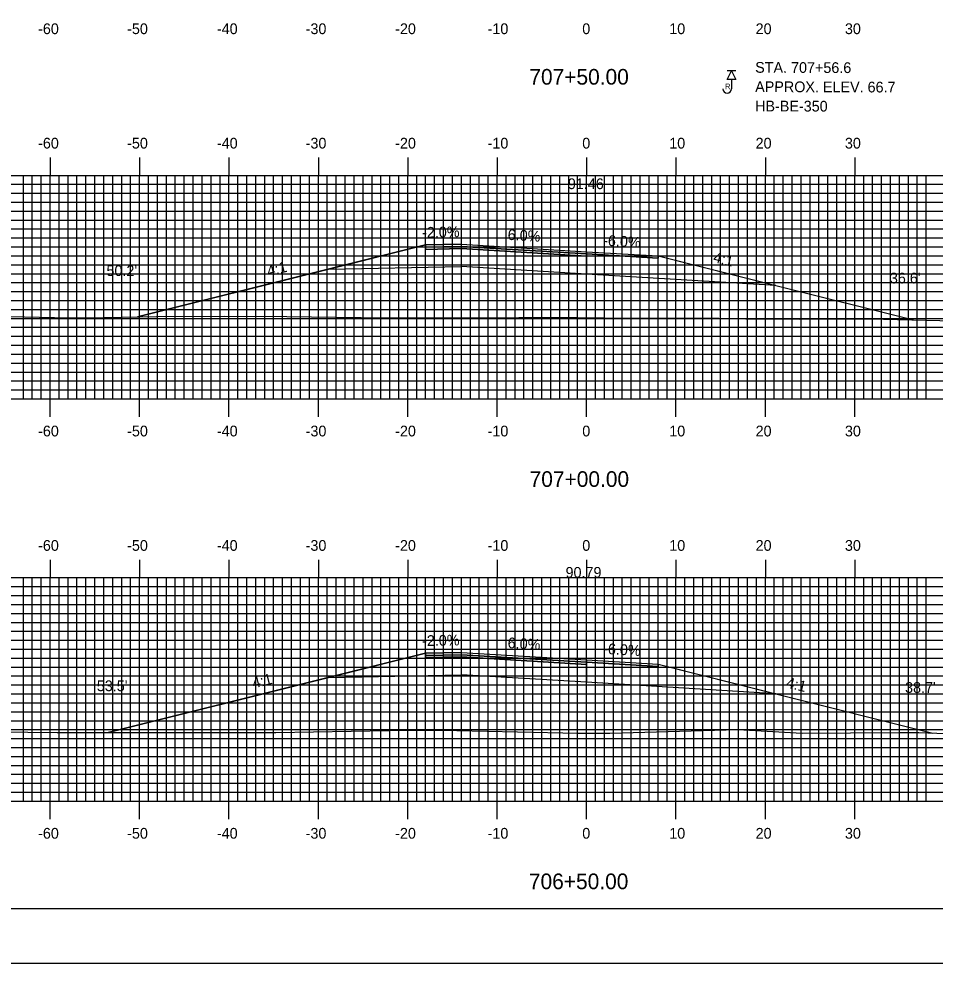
# Model space of a CAD drawing. Extents: x 854116 to 854460, y 364366 to 364586.
# Drawn here: x 854218.7 to 854321.2, y 364365.7 to 364471.3 of the extents above; entities that cross this region are included whole.
import ezdxf

# ---------------------------------------------------------------- set-up
doc = ezdxf.new("R2010")
doc.units = 0
for name, color, linetype in [('ANNOTATION', 7, 'Continuous'), ('BORDER', 7, 'Continuous'), ('BORING - REFUSAL', 7, 'Continuous'), ('D_Roadway_Centerline', 7, 'Continuous'), ('D_Roadway_Centerline_Text', 7, 'Continuous'), ('D_Roadway_Edge_Shoulder', 7, 'Continuous'), ('D_Roadway_Edge_TW', 7, 'Continuous'), ('D_Roadway_Pavement', 7, 'Continuous'), ('D_Roadway_SlopeLines', 7, 'Continuous'), ('D_Roadway_SubGrade', 7, 'Continuous'), ('D_Text_Standard', 7, 'Continuous'), ('H_V ANNOTATION', 7, 'Continuous'), ('MAJOR', 7, 'Continuous'), ('MINOR', 7, 'Continuous'), ('PLOT BOUNDARY', 7, 'Continuous'), ('S_Roadway_Centerline', 7, 'Continuous')]:
    doc.layers.add(name, color=color, linetype=linetype)

msp = doc.modelspace()

# ---------------------------------------------------------------- linework, layer by layer
at = {"layer": 'BORDER'}
msp.add_lwpolyline([(854132.63, 364371.79), (854452.63, 364371.79), (854452.63, 364581.79), (854132.63, 364581.79)], close=True, dxfattribs=at)
at = {"layer": 'BORING - REFUSAL'}
for p, q in [((854298.91, 364465.49), (854297.95, 364465.49)), ((854298.43, 364464.53), (854298.43, 364463.47))]:
    msp.add_line(p, q, dxfattribs=at)
msp.add_lwpolyline([(854298.43, 364465.49), (854298.91, 364464.53), (854297.95, 364464.53)], close=True, dxfattribs=at)
msp.add_arc((854297.95, 364463.47), 0.485, 180, 0, dxfattribs=at)
at = {"layer": 'D_Roadway_Centerline'}
for points in [[(854232, 364437.95), (854253.36, 364443.29), (854264.23, 364446.01), (854268.23, 364446.09), (854282.23, 364445.25), (854290.23, 364444.77), (854302.23, 364441.77), (854303.39, 364441.48), (854318.79, 364437.63)], [(854228.7, 364391.45), (854253.36, 364397.62), (854264.23, 364400.34), (854268.23, 364400.42), (854282.23, 364399.58), (854290.23, 364399.1), (854302.23, 364396.1), (854303.39, 364395.81), (854320.98, 364391.41)]]:
    msp.add_lwpolyline(points, dxfattribs=at)
at = {"layer": 'D_Roadway_Edge_Shoulder'}
for points in [[(854268.23, 364446.09), (854264.23, 364446.01), (854264.23, 364445.76), (854268.23, 364445.84)], [(854282.23, 364445.25), (854290.23, 364444.77), (854290.23, 364444.52), (854282.23, 364445)], [(854268.23, 364400.42), (854264.23, 364400.34), (854264.23, 364400.09), (854268.23, 364400.17)], [(854282.23, 364399.58), (854290.23, 364399.1), (854290.23, 364398.85), (854282.23, 364399.33)]]:
    msp.add_lwpolyline(points, close=True, dxfattribs=at)
at = {"layer": 'D_Roadway_Edge_TW'}
for points in [[(854268.23, 364446.09), (854282.23, 364445.25), (854282.23, 364445), (854268.23, 364445.84)], [(854268.23, 364400.42), (854282.23, 364399.58), (854282.23, 364399.33), (854268.23, 364400.17)]]:
    msp.add_lwpolyline(points, close=True, dxfattribs=at)
at = {"layer": 'D_Roadway_Pavement'}
for points in [[(854268.23, 364445.84), (854264.23, 364445.76), (854264.23, 364445.51), (854268.23, 364445.59)], [(854268.23, 364445.84), (854282.23, 364445), (854282.23, 364444.75), (854268.23, 364445.59)], [(854268.23, 364400.17), (854264.23, 364400.09), (854264.23, 364399.84), (854268.23, 364399.92)], [(854268.23, 364400.17), (854282.23, 364399.33), (854282.23, 364399.08), (854268.23, 364399.92)]]:
    msp.add_lwpolyline(points, close=True, dxfattribs=at)
for points in [[(854282.23, 364445), (854282.23, 364444.75)], [(854282.23, 364445), (854282.23, 364444.75)], [(854282.23, 364399.33), (854282.23, 364399.08)], [(854282.23, 364399.33), (854282.23, 364399.08)]]:
    msp.add_lwpolyline(points, dxfattribs=at)
at = {"layer": 'D_Roadway_SlopeLines'}
for points in [[(854264.23, 364446.01), (854232, 364437.95)], [(854290.23, 364444.77), (854303.39, 364441.48), (854318.79, 364437.63)], [(854264.23, 364400.34), (854228.7, 364391.45)], [(854290.23, 364399.1), (854303.39, 364395.81), (854320.98, 364391.41)]]:
    msp.add_lwpolyline(points, dxfattribs=at)
at = {"layer": 'D_Roadway_SubGrade'}
for points in [[(854268.23, 364445.59), (854264.23, 364445.51), (854264.23, 364445.76), (854264.23, 364446.01), (854253.36, 364443.29), (854268.23, 364443.59)], [(854268.23, 364445.59), (854282.23, 364444.75), (854282.23, 364442.75), (854268.23, 364443.59)], [(854282.23, 364444.75), (854282.23, 364445), (854290.23, 364444.52), (854290.23, 364444.77), (854303.39, 364441.48), (854282.23, 364442.75)], [(854268.23, 364399.92), (854264.23, 364399.84), (854264.23, 364400.09), (854264.23, 364400.34), (854253.36, 364397.62), (854268.23, 364397.92)], [(854268.23, 364399.92), (854282.23, 364399.08), (854282.23, 364397.08), (854268.23, 364397.92)], [(854282.23, 364399.08), (854282.23, 364399.33), (854290.23, 364398.85), (854290.23, 364399.1), (854303.39, 364395.81), (854282.23, 364397.08)]]:
    msp.add_lwpolyline(points, close=True, dxfattribs=at)
at = {"layer": 'MAJOR'}
for p, q in [((854222.23, 364455.79), (854222.23, 364453.79)), ((854232.23, 364455.79), (854232.23, 364453.79)), ((854242.23, 364455.79), (854242.23, 364453.79)), ((854252.23, 364455.79), (854252.23, 364453.79)), ((854262.23, 364455.79), (854262.23, 364453.79)), ((854272.23, 364455.79), (854272.23, 364453.79)), ((854282.23, 364455.79), (854282.23, 364453.79)), ((854292.23, 364455.79), (854292.23, 364453.79)), ((854302.23, 364455.79), (854302.23, 364453.79)), ((854312.23, 364455.79), (854312.23, 364453.79)), ((854142.23, 364453.79), (854422.23, 364453.79)), ((854142.23, 364453.79), (854422.23, 364453.79)), ((854222.23, 364428.79), (854222.23, 364453.79)), ((854232.23, 364428.79), (854232.23, 364453.79)), ((854242.23, 364428.79), (854242.23, 364453.79)), ((854252.23, 364428.79), (854252.23, 364453.79)), ((854262.23, 364428.79), (854262.23, 364453.79)), ((854272.23, 364428.79), (854272.23, 364453.79)), ((854282.23, 364428.79), (854282.23, 364453.79)), ((854292.23, 364428.79), (854292.23, 364453.79)), ((854302.23, 364428.79), (854302.23, 364453.79)), ((854312.23, 364428.79), (854312.23, 364453.79)), ((854142.23, 364448.79), (854422.23, 364448.79)), ((854142.23, 364443.79), (854422.23, 364443.79)), ((854142.23, 364438.79), (854422.23, 364438.79)), ((854142.23, 364433.79), (854422.23, 364433.79)), ((854142.23, 364428.79), (854422.23, 364428.79)), ((854142.23, 364428.79), (854422.23, 364428.79)), ((854222.23, 364426.78), (854222.23, 364428.79)), ((854232.23, 364426.78), (854232.23, 364428.79)), ((854242.23, 364426.78), (854242.23, 364428.79)), ((854252.23, 364426.78), (854252.23, 364428.79)), ((854262.23, 364426.78), (854262.23, 364428.79)), ((854272.23, 364426.78), (854272.23, 364428.79)), ((854282.23, 364426.78), (854282.23, 364428.79)), ((854292.23, 364426.78), (854292.23, 364428.79)), ((854302.23, 364426.78), (854302.23, 364428.79)), ((854312.23, 364426.78), (854312.23, 364428.79)), ((854222.23, 364410.79), (854222.23, 364408.79)), ((854232.23, 364410.79), (854232.23, 364408.79)), ((854242.23, 364410.79), (854242.23, 364408.79)), ((854252.23, 364410.79), (854252.23, 364408.79)), ((854262.23, 364410.79), (854262.23, 364408.79)), ((854272.23, 364410.79), (854272.23, 364408.79)), ((854282.23, 364410.79), (854282.23, 364408.79)), ((854292.23, 364410.79), (854292.23, 364408.79)), ((854302.23, 364410.79), (854302.23, 364408.79)), ((854312.23, 364410.79), (854312.23, 364408.79)), ((854142.23, 364408.79), (854422.23, 364408.79)), ((854142.23, 364408.79), (854422.23, 364408.79)), ((854222.23, 364383.79), (854222.23, 364408.79)), ((854232.23, 364383.79), (854232.23, 364408.79)), ((854242.23, 364383.79), (854242.23, 364408.79)), ((854252.23, 364383.79), (854252.23, 364408.79)), ((854262.23, 364383.79), (854262.23, 364408.79)), ((854272.23, 364383.79), (854272.23, 364408.79)), ((854282.23, 364383.79), (854282.23, 364408.79)), ((854292.23, 364383.79), (854292.23, 364408.79)), ((854302.23, 364383.79), (854302.23, 364408.79)), ((854312.23, 364383.79), (854312.23, 364408.79)), ((854142.23, 364403.79), (854422.23, 364403.79)), ((854142.23, 364398.79), (854422.23, 364398.79)), ((854142.23, 364393.79), (854422.23, 364393.79)), ((854142.23, 364388.79), (854422.23, 364388.79)), ((854142.23, 364383.79), (854422.23, 364383.79)), ((854142.23, 364383.79), (854422.23, 364383.79)), ((854222.23, 364381.78), (854222.23, 364383.79)), ((854232.23, 364381.78), (854232.23, 364383.79)), ((854242.23, 364381.78), (854242.23, 364383.79)), ((854252.23, 364381.78), (854252.23, 364383.79)), ((854262.23, 364381.78), (854262.23, 364383.79)), ((854272.23, 364381.78), (854272.23, 364383.79)), ((854282.23, 364381.78), (854282.23, 364383.79)), ((854292.23, 364381.78), (854292.23, 364383.79)), ((854302.23, 364381.78), (854302.23, 364383.79)), ((854312.23, 364381.78), (854312.23, 364383.79))]:
    msp.add_line(p, q, dxfattribs=at)
at = {"layer": 'MINOR'}
for p, q in [((854219.23, 364428.79), (854219.23, 364453.79)), ((854220.23, 364428.79), (854220.23, 364453.79)), ((854221.23, 364428.79), (854221.23, 364453.79)), ((854223.23, 364428.79), (854223.23, 364453.79)), ((854224.23, 364428.79), (854224.23, 364453.79)), ((854225.23, 364428.79), (854225.23, 364453.79)), ((854226.23, 364428.79), (854226.23, 364453.79)), ((854227.23, 364428.79), (854227.23, 364453.79)), ((854228.23, 364428.79), (854228.23, 364453.79)), ((854229.23, 364428.79), (854229.23, 364453.79)), ((854230.23, 364428.79), (854230.23, 364453.79)), ((854231.23, 364428.79), (854231.23, 364453.79)), ((854233.23, 364428.79), (854233.23, 364453.79)), ((854234.23, 364428.79), (854234.23, 364453.79)), ((854235.23, 364428.79), (854235.23, 364453.79)), ((854236.23, 364428.79), (854236.23, 364453.79)), ((854237.23, 364428.79), (854237.23, 364453.79)), ((854238.23, 364428.79), (854238.23, 364453.79)), ((854239.23, 364428.79), (854239.23, 364453.79)), ((854240.23, 364428.79), (854240.23, 364453.79)), ((854241.23, 364428.79), (854241.23, 364453.79)), ((854243.23, 364428.79), (854243.23, 364453.79)), ((854244.23, 364428.79), (854244.23, 364453.79)), ((854245.23, 364428.79), (854245.23, 364453.79)), ((854246.23, 364428.79), (854246.23, 364453.79)), ((854247.23, 364428.79), (854247.23, 364453.79)), ((854248.23, 364428.79), (854248.23, 364453.79)), ((854249.23, 364428.79), (854249.23, 364453.79)), ((854250.23, 364428.79), (854250.23, 364453.79)), ((854251.23, 364428.79), (854251.23, 364453.79)), ((854253.23, 364428.79), (854253.23, 364453.79)), ((854254.23, 364428.79), (854254.23, 364453.79)), ((854255.23, 364428.79), (854255.23, 364453.79)), ((854256.23, 364428.79), (854256.23, 364453.79)), ((854257.23, 364428.79), (854257.23, 364453.79)), ((854258.23, 364428.79), (854258.23, 364453.79)), ((854259.23, 364428.79), (854259.23, 364453.79)), ((854260.23, 364428.79), (854260.23, 364453.79)), ((854261.23, 364428.79), (854261.23, 364453.79)), ((854263.23, 364428.79), (854263.23, 364453.79)), ((854264.23, 364428.79), (854264.23, 364453.79)), ((854265.23, 364428.79), (854265.23, 364453.79)), ((854266.23, 364428.79), (854266.23, 364453.79)), ((854267.23, 364428.79), (854267.23, 364453.79)), ((854268.23, 364428.79), (854268.23, 364453.79)), ((854269.23, 364428.79), (854269.23, 364453.79)), ((854270.23, 364428.79), (854270.23, 364453.79)), ((854271.23, 364428.79), (854271.23, 364453.79)), ((854273.23, 364428.79), (854273.23, 364453.79)), ((854274.23, 364428.79), (854274.23, 364453.79)), ((854275.23, 364428.79), (854275.23, 364453.79)), ((854276.23, 364428.79), (854276.23, 364453.79)), ((854277.23, 364428.79), (854277.23, 364453.79)), ((854278.23, 364428.79), (854278.23, 364453.79)), ((854279.23, 364428.79), (854279.23, 364453.79)), ((854280.23, 364428.79), (854280.23, 364453.79)), ((854281.23, 364428.79), (854281.23, 364453.79)), ((854283.23, 364428.79), (854283.23, 364453.79)), ((854284.23, 364428.79), (854284.23, 364453.79)), ((854285.23, 364428.79), (854285.23, 364453.79)), ((854286.23, 364428.79), (854286.23, 364453.79)), ((854287.23, 364428.79), (854287.23, 364453.79)), ((854288.23, 364428.79), (854288.23, 364453.79)), ((854289.23, 364428.79), (854289.23, 364453.79)), ((854290.23, 364428.79), (854290.23, 364453.79)), ((854291.23, 364428.79), (854291.23, 364453.79)), ((854293.23, 364428.79), (854293.23, 364453.79)), ((854294.23, 364428.79), (854294.23, 364453.79)), ((854295.23, 364428.79), (854295.23, 364453.79)), ((854296.23, 364428.79), (854296.23, 364453.79)), ((854297.23, 364428.79), (854297.23, 364453.79)), ((854298.23, 364428.79), (854298.23, 364453.79)), ((854299.23, 364428.79), (854299.23, 364453.79)), ((854300.23, 364428.79), (854300.23, 364453.79)), ((854301.23, 364428.79), (854301.23, 364453.79)), ((854303.23, 364428.79), (854303.23, 364453.79)), ((854304.23, 364428.79), (854304.23, 364453.79)), ((854305.23, 364428.79), (854305.23, 364453.79)), ((854306.23, 364428.79), (854306.23, 364453.79)), ((854307.23, 364428.79), (854307.23, 364453.79)), ((854308.23, 364428.79), (854308.23, 364453.79)), ((854309.23, 364428.79), (854309.23, 364453.79)), ((854310.23, 364428.79), (854310.23, 364453.79)), ((854311.23, 364428.79), (854311.23, 364453.79)), ((854313.23, 364428.79), (854313.23, 364453.79)), ((854314.23, 364428.79), (854314.23, 364453.79)), ((854315.23, 364428.79), (854315.23, 364453.79)), ((854316.23, 364428.79), (854316.23, 364453.79)), ((854317.23, 364428.79), (854317.23, 364453.79)), ((854318.23, 364428.79), (854318.23, 364453.79)), ((854319.23, 364428.79), (854319.23, 364453.79)), ((854320.23, 364428.79), (854320.23, 364453.79)), ((854142.23, 364452.79), (854422.23, 364452.79)), ((854142.23, 364451.79), (854422.23, 364451.79)), ((854142.23, 364450.79), (854422.23, 364450.79)), ((854142.23, 364449.79), (854422.23, 364449.79)), ((854142.23, 364447.79), (854422.23, 364447.79)), ((854142.23, 364446.79), (854422.23, 364446.79)), ((854142.23, 364445.79), (854422.23, 364445.79)), ((854142.23, 364444.79), (854422.23, 364444.79)), ((854142.23, 364442.79), (854422.23, 364442.79)), ((854142.23, 364441.79), (854422.23, 364441.79)), ((854142.23, 364440.79), (854422.23, 364440.79)), ((854142.23, 364439.79), (854422.23, 364439.79)), ((854142.23, 364437.79), (854422.23, 364437.79)), ((854142.23, 364436.79), (854422.23, 364436.79)), ((854142.23, 364435.79), (854422.23, 364435.79)), ((854142.23, 364434.79), (854422.23, 364434.79)), ((854142.23, 364432.79), (854422.23, 364432.79)), ((854142.23, 364431.79), (854422.23, 364431.79)), ((854142.23, 364430.79), (854422.23, 364430.79)), ((854142.23, 364429.79), (854422.23, 364429.79)), ((854219.23, 364383.79), (854219.23, 364408.79)), ((854220.23, 364383.79), (854220.23, 364408.79)), ((854221.23, 364383.79), (854221.23, 364408.79)), ((854223.23, 364383.79), (854223.23, 364408.79)), ((854224.23, 364383.79), (854224.23, 364408.79)), ((854225.23, 364383.79), (854225.23, 364408.79)), ((854226.23, 364383.79), (854226.23, 364408.79)), ((854227.23, 364383.79), (854227.23, 364408.79)), ((854228.23, 364383.79), (854228.23, 364408.79)), ((854229.23, 364383.79), (854229.23, 364408.79)), ((854230.23, 364383.79), (854230.23, 364408.79)), ((854231.23, 364383.79), (854231.23, 364408.79)), ((854233.23, 364383.79), (854233.23, 364408.79)), ((854234.23, 364383.79), (854234.23, 364408.79)), ((854235.23, 364383.79), (854235.23, 364408.79)), ((854236.23, 364383.79), (854236.23, 364408.79)), ((854237.23, 364383.79), (854237.23, 364408.79)), ((854238.23, 364383.79), (854238.23, 364408.79)), ((854239.23, 364383.79), (854239.23, 364408.79)), ((854240.23, 364383.79), (854240.23, 364408.79)), ((854241.23, 364383.79), (854241.23, 364408.79)), ((854243.23, 364383.79), (854243.23, 364408.79)), ((854244.23, 364383.79), (854244.23, 364408.79)), ((854245.23, 364383.79), (854245.23, 364408.79)), ((854246.23, 364383.79), (854246.23, 364408.79)), ((854247.23, 364383.79), (854247.23, 364408.79)), ((854248.23, 364383.79), (854248.23, 364408.79)), ((854249.23, 364383.79), (854249.23, 364408.79)), ((854250.23, 364383.79), (854250.23, 364408.79)), ((854251.23, 364383.79), (854251.23, 364408.79)), ((854253.23, 364383.79), (854253.23, 364408.79)), ((854254.23, 364383.79), (854254.23, 364408.79)), ((854255.23, 364383.79), (854255.23, 364408.79)), ((854256.23, 364383.79), (854256.23, 364408.79)), ((854257.23, 364383.79), (854257.23, 364408.79)), ((854258.23, 364383.79), (854258.23, 364408.79)), ((854259.23, 364383.79), (854259.23, 364408.79)), ((854260.23, 364383.79), (854260.23, 364408.79)), ((854261.23, 364383.79), (854261.23, 364408.79)), ((854263.23, 364383.79), (854263.23, 364408.79)), ((854264.23, 364383.79), (854264.23, 364408.79)), ((854265.23, 364383.79), (854265.23, 364408.79)), ((854266.23, 364383.79), (854266.23, 364408.79)), ((854267.23, 364383.79), (854267.23, 364408.79)), ((854268.23, 364383.79), (854268.23, 364408.79)), ((854269.23, 364383.79), (854269.23, 364408.79)), ((854270.23, 364383.79), (854270.23, 364408.79)), ((854271.23, 364383.79), (854271.23, 364408.79)), ((854273.23, 364383.79), (854273.23, 364408.79)), ((854274.23, 364383.79), (854274.23, 364408.79)), ((854275.23, 364383.79), (854275.23, 364408.79)), ((854276.23, 364383.79), (854276.23, 364408.79)), ((854277.23, 364383.79), (854277.23, 364408.79)), ((854278.23, 364383.79), (854278.23, 364408.79)), ((854279.23, 364383.79), (854279.23, 364408.79)), ((854280.23, 364383.79), (854280.23, 364408.79)), ((854281.23, 364383.79), (854281.23, 364408.79)), ((854283.23, 364383.79), (854283.23, 364408.79)), ((854284.23, 364383.79), (854284.23, 364408.79)), ((854285.23, 364383.79), (854285.23, 364408.79)), ((854286.23, 364383.79), (854286.23, 364408.79)), ((854287.23, 364383.79), (854287.23, 364408.79)), ((854288.23, 364383.79), (854288.23, 364408.79)), ((854289.23, 364383.79), (854289.23, 364408.79)), ((854290.23, 364383.79), (854290.23, 364408.79)), ((854291.23, 364383.79), (854291.23, 364408.79)), ((854293.23, 364383.79), (854293.23, 364408.79)), ((854294.23, 364383.79), (854294.23, 364408.79)), ((854295.23, 364383.79), (854295.23, 364408.79)), ((854296.23, 364383.79), (854296.23, 364408.79)), ((854297.23, 364383.79), (854297.23, 364408.79)), ((854298.23, 364383.79), (854298.23, 364408.79)), ((854299.23, 364383.79), (854299.23, 364408.79)), ((854300.23, 364383.79), (854300.23, 364408.79)), ((854301.23, 364383.79), (854301.23, 364408.79)), ((854303.23, 364383.79), (854303.23, 364408.79)), ((854304.23, 364383.79), (854304.23, 364408.79)), ((854305.23, 364383.79), (854305.23, 364408.79)), ((854306.23, 364383.79), (854306.23, 364408.79)), ((854307.23, 364383.79), (854307.23, 364408.79)), ((854308.23, 364383.79), (854308.23, 364408.79)), ((854309.23, 364383.79), (854309.23, 364408.79)), ((854310.23, 364383.79), (854310.23, 364408.79)), ((854311.23, 364383.79), (854311.23, 364408.79)), ((854313.23, 364383.79), (854313.23, 364408.79)), ((854314.23, 364383.79), (854314.23, 364408.79)), ((854315.23, 364383.79), (854315.23, 364408.79)), ((854316.23, 364383.79), (854316.23, 364408.79)), ((854317.23, 364383.79), (854317.23, 364408.79)), ((854318.23, 364383.79), (854318.23, 364408.79)), ((854319.23, 364383.79), (854319.23, 364408.79)), ((854320.23, 364383.79), (854320.23, 364408.79)), ((854142.23, 364407.79), (854422.23, 364407.79)), ((854142.23, 364406.79), (854422.23, 364406.79)), ((854142.23, 364405.79), (854422.23, 364405.79)), ((854142.23, 364404.79), (854422.23, 364404.79)), ((854142.23, 364402.79), (854422.23, 364402.79)), ((854142.23, 364401.79), (854422.23, 364401.79)), ((854142.23, 364400.79), (854422.23, 364400.79)), ((854142.23, 364399.79), (854422.23, 364399.79)), ((854142.23, 364397.79), (854422.23, 364397.79)), ((854142.23, 364396.79), (854422.23, 364396.79)), ((854142.23, 364395.79), (854422.23, 364395.79)), ((854142.23, 364394.79), (854422.23, 364394.79)), ((854142.23, 364392.79), (854422.23, 364392.79)), ((854142.23, 364391.79), (854422.23, 364391.79)), ((854142.23, 364390.79), (854422.23, 364390.79)), ((854142.23, 364389.79), (854422.23, 364389.79)), ((854142.23, 364387.79), (854422.23, 364387.79)), ((854142.23, 364386.79), (854422.23, 364386.79)), ((854142.23, 364385.79), (854422.23, 364385.79)), ((854142.23, 364384.79), (854422.23, 364384.79))]:
    msp.add_line(p, q, dxfattribs=at)
at = {"layer": 'PLOT BOUNDARY'}
msp.add_lwpolyline([(854116.44, 364365.67), (854456.44, 364365.67), (854456.44, 364585.67), (854116.44, 364585.67)], close=True, dxfattribs=at)
at = {"layer": 'S_Roadway_Centerline'}
for points in [[(854212.58, 364438.11), (854222.7, 364437.89), (854226.32, 364437.85), (854234.11, 364437.99), (854241.68, 364438.03), (854248.7, 364437.99), (854259.76, 364437.85), (854263.73, 364437.87), (854271.04, 364437.86), (854278.26, 364437.91), (854287.08, 364437.82), (854297.03, 364437.81), (854300.06, 364437.74), (854306.04, 364437.72), (854312.3, 364437.74), (854315.45, 364437.71), (854326.49, 364437.44)], [(854213.12, 364391.56), (854223.01, 364391.45), (854230.42, 364391.45), (854241.72, 364391.46), (854247.49, 364391.45), (854260.12, 364391.68), (854265.2, 364391.74), (854267.73, 364391.69), (854274.52, 364391.54), (854281.27, 364391.4), (854284.84, 364391.41), (854299.17, 364391.81), (854306.34, 364391.38), (854317.17, 364391.45), (854319.39, 364391.47), (854327.49, 364391.18)]]:
    msp.add_lwpolyline(points, dxfattribs=at)

# ---------------------------------------------------------------- texts
at = {"layer": 'ANNOTATION'}
for s, rotation, p in [('-2.0%', 1.1458, (854263.84, 364446.8)), ('6.0%', 356.5664, (854273.38, 364446.58)), ('-6.0%', 356.5664, (854284.06, 364445.94)), ('4:1', 345.9638, (854296.32, 364444.11)), ('4:1', 14.0362, (854246.65, 364442.48)), ('-2.0%', 1.1458, (854263.84, 364401.13)), ('6.0%', 356.5664, (854273.38, 364400.91)), ('-6.0%', 356.5664, (854284.06, 364400.27)), ('4:1', 14.0362, (854245, 364396.39)), ('4:1', 345.9638, (854304.48, 364396.52))]:
    msp.add_text(s, height=1.2, rotation=rotation, dxfattribs=at).set_placement(p)
at = {"layer": 'BORING - REFUSAL'}
for s, p in [('STA. 707+56.6', (854301.09, 364465.27)), ('APPROX. ELEV. 66.7', (854301.09, 364463.11)), ('HB-BE-350', (854301.08, 364460.95))]:
    msp.add_text(s, height=1.2, rotation=359.8142, dxfattribs=at).set_placement(p)
msp.add_text('R', height=0.64, dxfattribs=at).set_placement((854297.72, 364463.41))
at = {"layer": 'D_Roadway_Centerline_Text'}
for s, p in [('91.46', (854280.14, 364452.25)), ('90.79', (854279.88, 364408.78))]:
    msp.add_text(s, height=1.2, dxfattribs=at).set_placement(p)
at = {"layer": 'D_Text_Standard'}
for s, p in [("50.2'", (854228.53, 364442.53)), ("36.6'", (854316.16, 364441.7)), ("53.5'", (854227.45, 364396.09)), ("38.7'", (854317.86, 364395.9))]:
    msp.add_text(s, height=1.2, dxfattribs=at).set_placement(p)
at = {"layer": 'H_V ANNOTATION'}
for s, height, p in [('-60', 1.2, (854220.88, 364469.59)), ('-50', 1.2, (854230.84, 364469.59)), ('-40', 1.2, (854240.88, 364469.59)), ('-30', 1.2, (854250.81, 364469.59)), ('-20', 1.2, (854260.82, 364469.59)), ('-10', 1.2, (854271.16, 364469.59)), ('0', 1.2, (854281.75, 364469.59)), ('10', 1.2, (854291.48, 364469.59)), ('20', 1.2, (854301.14, 364469.59)), ('30', 1.2, (854311.13, 364469.59)), ('707+50.00', 1.75, (854275.83, 364463.94)), ('-60', 1.2, (854220.88, 364456.79)), ('-50', 1.2, (854230.84, 364456.79)), ('-40', 1.2, (854240.88, 364456.79)), ('-30', 1.2, (854250.81, 364456.79)), ('-20', 1.2, (854260.82, 364456.79)), ('-10', 1.2, (854271.16, 364456.79)), ('0', 1.2, (854281.75, 364456.79)), ('10', 1.2, (854291.48, 364456.79)), ('20', 1.2, (854301.14, 364456.79)), ('30', 1.2, (854311.13, 364456.79)), ('-60', 1.2, (854220.88, 364424.59)), ('-50', 1.2, (854230.84, 364424.59)), ('-40', 1.2, (854240.88, 364424.59)), ('-30', 1.2, (854250.81, 364424.59)), ('-20', 1.2, (854260.82, 364424.59)), ('-10', 1.2, (854271.16, 364424.59)), ('0', 1.2, (854281.75, 364424.59)), ('10', 1.2, (854291.48, 364424.59)), ('20', 1.2, (854301.14, 364424.59)), ('30', 1.2, (854311.13, 364424.59)), ('707+00.00', 1.75, (854275.86, 364418.94)), ('-60', 1.2, (854220.88, 364411.79)), ('-50', 1.2, (854230.84, 364411.79)), ('-40', 1.2, (854240.88, 364411.79)), ('-30', 1.2, (854250.81, 364411.79)), ('-20', 1.2, (854260.82, 364411.79)), ('-10', 1.2, (854271.16, 364411.79)), ('0', 1.2, (854281.75, 364411.79)), ('10', 1.2, (854291.48, 364411.79)), ('20', 1.2, (854301.14, 364411.79)), ('30', 1.2, (854311.13, 364411.79)), ('-60', 1.2, (854220.88, 364379.59)), ('-50', 1.2, (854230.84, 364379.59)), ('-40', 1.2, (854240.88, 364379.59)), ('-30', 1.2, (854250.81, 364379.59)), ('-20', 1.2, (854260.82, 364379.59)), ('-10', 1.2, (854271.16, 364379.59)), ('0', 1.2, (854281.75, 364379.59)), ('10', 1.2, (854291.48, 364379.59)), ('20', 1.2, (854301.14, 364379.59)), ('30', 1.2, (854311.13, 364379.59)), ('706+50.00', 1.75, (854275.78, 364373.94))]:
    msp.add_text(s, height=height, dxfattribs=at).set_placement(p)

doc.saveas('drawing.dxf')
